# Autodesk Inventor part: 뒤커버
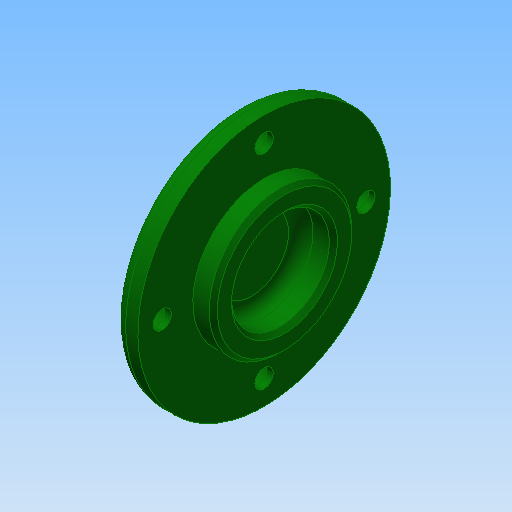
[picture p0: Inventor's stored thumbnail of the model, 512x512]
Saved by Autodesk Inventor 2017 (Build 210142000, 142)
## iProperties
Created: 2015-12
Part Number: 뒤커버
Document SubType Name: Modeling
Designer: mdu
Density: 2.71 g/cm^3
Material: 알루미늄 6061
Mass: 56.2003 g
Surface Area: 84.0408 cm^2
Volume: 20.7381 cm^3
Appearance: 진녹색
Author: mdu
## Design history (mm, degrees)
sketch "스케치1"
  geometry: L1 (-7, 0)-(7, 0); L2 (-7, 0)-(-7, 15.539); L3 (-7, 15.539)-(-4, 18.5); L4 (-4, 18.5)-(-4, 31); L5 (-4, 31)-(2, 31); L6 (2, 31)-(2, 17.5); L7 (2, 17.5)-(7, 17.5); L8 (7, 17.5)-(7, 0); 2 further points
  constraints: 16 end point, 4 parallel, 2 perpendicular, 1 coincident, 1 horizontal, 1 midpoint
  dimensions: "d0" = 14 distance of L1.start L1.end; "d1" = 62 diameter of L5 L1; "d2" = 35 diameter of L7 L1; "d3" = 37 diameter of L3.end L1; "d4" = 3 distance between parallel lines of L4 L2; "d5" = 6 distance of L4.end L5.end
revolve "회전1" sketch "스케치1" stored, may be unused: angle "d6" = 90 deg
sketch "스케치2" dims "d32" = 50
  geometry: 3 further points
  constraints: 2 vertical alignment, 1 coincident, 2 other
hole "구멍1" sketch "스케치2" at (0, 25) diameter "d8" = 4.5; stored, may be unused: countersink angle "d12" = 90 deg, drill point angle "d14" = 118 deg; dims "d9" = 6, "d10" = 8, "d11" = 4.4, "d13" = 8
hole "구멍2" diameter "d20" = 24; stored, may be unused: countersink angle "d24" = 90 deg, drill point angle "d26" = 0 deg; dims "d18" = 10, "d19" = 10, "d21" = 6, "d22" = 8, "d23" = 4.4, "d25" = 8
fillet "모깎기1" dims "d27" = 3
fillet "모깎기2" dims "d28" = 3
chamfer "모따기1" distance "d29" = 1; stored, may be unused: second distance "d30" = 2, angle "d31" = 45 deg
node "솔리드1"
pattern_circular "원형 패턴1" dims angle "d16" = 360 deg
